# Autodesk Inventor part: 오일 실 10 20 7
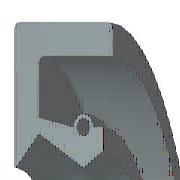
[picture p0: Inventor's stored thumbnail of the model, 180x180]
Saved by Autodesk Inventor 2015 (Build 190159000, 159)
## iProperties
IsCustomPart: 1
Created: 2012-02
Part Number: 오일 실 10 20 7
Material: 고무
Description: 오일-실
Document SubType Name: Modeling
Standard: KS B 2804
Designer: mduedu
Standards Organization: KS
Language: ko-KR
Size Designation: D - 10 20 7
Categories: <MemberInstance><Categories><Category DisplayName="샤프트 부품" InternalName="7f7aeb1f-a693-4053-b835-cee3144e0d98" Mnemonic="SHFT"><Category DisplayName="실링" Intern
Density: 0.93 g/cm^3
Appearance: 고무 - 검은색 - 버전 1.1
Author: mduedu
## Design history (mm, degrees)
revolve "본체" stored, may be unused: angle "d17" = 90 deg
revolve "스프링1" stored, may be unused: angle "d18" = 90 deg
body "Solid1"
sketch "스케치1"
  geometry: L1 (0, 10)-(7, 10); L2 (7, 8.25)-(1.75, 8.25); L3 (1.75, 6.75)-(4.9, 5); L4 (4.9, 5)-(0, 5); L5 (0, 0)-(9.586, 0) reference; L6 (4.9, 5)-(6.3, 5.875); L7 (0, 18)-(0, -3) reference; L8 (-1.941, 0)-(11.507, 0) reference; L9 (4.2, 7.1)-(1.75, 7.59); L10 (1.75, 7.59)-(1.75, 8.25); L11 (0, 10)-(0, 5.088); L12 (4.9, 5)-(0, 5); L13 (1.75, 6.75)-(0.152, 5.028); L14 (7, 10)-(7, 8.25); L15 (5.6, 7.1)-(6.3, 7.1); L16 (6.3, 7.1)-(6.3, 5.875); C1 r 0.455 at (4.9, 7.1); A1 r 0.7 centre (4.9, 7.1) between (5.6, 7.1) and (4.2, 7.1); A2 r 0.088 centre (0.088, 5.088) between (0, 5.088) and (0.152, 5.028); 1 further point
  constraints: 28 end point, 5 horizontal alignment, 5 point on line, 4 point on circle, 4 vertical alignment, 3 centre point, 3 tangent, 2 collinear, 2 horizontal, 2 perpendicular, 1 coincident, 1 parallel
  dimensions: "d0" = 20 diameter of L1 L5 (= SD2); "d1" = 1.75 distance of L1.end L2.start (= SD); "d2" = 0.91 diameter of C1 (= SPDI); "d3" = 1.4 diameter of A1 (= SPDA); "d4" = 10 diameter of L3.end L5 (= NND); "d5" = 13.5 diameter of L3.start L5 (= TKDM); "d7" = 15.18 diameter of L9.end L5 (= TKDM + 0.24 x SWDT); "d8" = 1.75 distance between parallel lines of L11 L10 (= SD); "d9" = 4.9 distance from line of L11 C1.centre (= SPDST); "d10" = 14.2 diameter of C1.centre L5 (= HLDM); "d11" = 0.0875 radius of A2 (= 0.25 x LAB); "d12" = 6.3 distance between parallel lines of L11 L16 (= SDI); "d13" = 11.75 diameter of L6.end L5 (= ABDM); "d14" = 7 distance from line of L11 L1.end (= SWDT)
fillet "모깎기1" dims "d6" = 0.3 (= RR)
other parameters: "SD2" = 20 [user parameter; used in 1 equation term], "SWDT" = 7 [user parameter; used in 2 equation terms], "RR" = 0.3 [user parameter; used in 1 equation term], "SD" = 1.75 [user parameter; used in 2 equation terms], "NND" = 10 [user parameter; used in 1 equation term], "SPDA" = 1.4 [user parameter; used in 1 equation term], "SPDI" = 0.91 [user parameter; used in 1 equation term], "TKDM" = 13.5 [user parameter; used in 2 equation terms], "HLDM" = 14.2 [user parameter; used in 1 equation term], "ABDM" = 11.75 [user parameter; used in 1 equation term], "SDI" = 6.3 [user parameter; used in 1 equation term], "SPDST" = 4.9 [user parameter; used in 1 equation term], "LAB" = 0.35 [user parameter; used in 1 equation term], "d15" = 0, "d16" = 0, "d19" = 0
